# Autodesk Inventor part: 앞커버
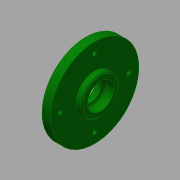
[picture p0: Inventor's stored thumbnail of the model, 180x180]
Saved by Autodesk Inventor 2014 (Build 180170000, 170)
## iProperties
Created: 2015-09
Part Number: 앞커버
Material: 알루미늄 6061
Document SubType Name: Modeling
Designer: mduedu
Density: 2.71 g/cm^3
Mass: 58.9874 g
Surface Area: 98.7754 cm^2
Volume: 21.7666 cm^3
Appearance: 진녹색
Author: mduedu
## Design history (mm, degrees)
sketch "스케치1"
  geometry: L1 (-6.5, 63)-(-11.5, 63); L2 (-11.5, 63)-(-11.5, 84.5); L3 (-11.5, 84.5)-(-19.5, 84.5); L4 (-19.5, 84.5)-(-19.5, 70.5); L5 (-24.5, 70.5)-(-24.5, 54.5); L6 (-24.5, 54.5)-(-6.5, 54.5); L7 (-6.5, 54.5)-(-6.5, 63); L8 (-79.5, 39.5)-(-79.5, 54.5) reference; L9 (48.5, 54.5)-(48.5, 39.5) reference; L10 (-79.5, 47)-(48.5, 47); L11 (-19.5, 70.5)-(-24.5, 70.5); 3 further points
  constraints: 18 end point, 6 parallel, 4 midpoint, 1 horizontal, 1 perpendicular, 1 vertical alignment
  dimensions: "d0" = 18 distance between parallel lines of L7 L5; "d3" = 32 diameter of L1 L10; "d5" = 5 distance of L1.start L1.end; "d6" = 75 diameter of L3 L10; "d7" = 8 distance of L2.end L3.end; "d8" = 47 diameter of L4.end L10; "d61" = 15 diameter of L6 L10
revolve "회전1" sketch "스케치1" stored, may be unused: angle "d4" = 90 deg
sketch "스케치2"
  geometry: C1 r 37.5 at (0, 0) reference; 2 further points
  constraints: 1 coincident
hole "구멍1" sketch "스케치2" at (0, 0) diameter "d11" = 22; stored, may be unused: countersink angle "d15" = 90 deg, drill point angle "d17" = 0 deg; dims "d12" = 6, "d13" = 4, "d14" = 2, "d16" = 8
fillet "모깎기1" dims "d18" = 3
fillet "모깎기2" dims "d19" = 1
sketch "스케치3"
  geometry: C1 r 37.5 at (0, 0) reference; 2 further points
  constraints: 1 coincident
hole "구멍2" sketch "스케치3" at (0, 0) diameter "d20" = 30; stored, may be unused: countersink angle "d24" = 90 deg, drill point angle "d26" = 0 deg; dims "d21" = 6, "d22" = 4, "d23" = 2, "d25" = 7.5
fillet "모깎기3" dims "d27" = 0.3
chamfer "모따기1" distance "d28" = 1; stored, may be unused: second distance "d29" = 2, angle "d30" = 30 deg
sketch "스케치7" dims "d56" = 58
  geometry: C1 r 37.5 at (0, 0) reference; 5 further points
  constraints: 2 vertical alignment, 1 coincident, 7 other
  dimensions: "d59" = 360 deg dimension on C1.centre point (0, 29) (derived)
hole "구멍4" sketch "스케치7" at (0, 29), (-29, 0), (0, -29), (29, 0) diameter "d48" = 3.4; stored, may be unused: countersink angle "d52" = 90 deg, drill point angle "d54" = 0 deg; dims "d49" = 6, "d50" = 6.5, "d51" = 3.4, "d53" = 8
hole "구멍5" diameter "d64" = 17; stored, may be unused: countersink angle "d68" = 90 deg, drill point angle "d70" = 118 deg; dims "d62" = 10, "d63" = 10, "d65" = 6, "d66" = 4, "d67" = 2, "d69" = 8
chamfer "모따기2" distance "d71" = 1; stored, may be unused: second distance "d72" = 2, angle "d73" = 45 deg
node "솔리드1"
node "참조1"
node "참조2"
